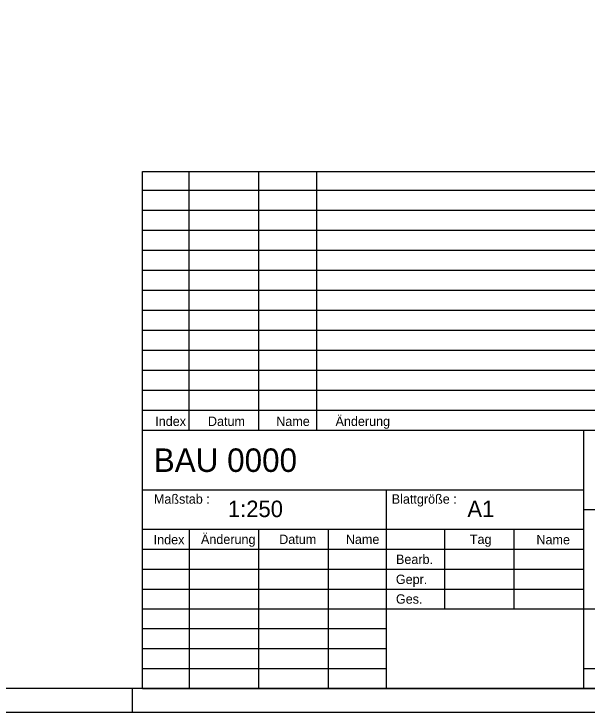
# Model space of a CAD drawing. Extents: x 0 to 210, y 0 to 148.
# Drawn here: x 157.69 to 188.16, y 0 to 37.12 of the extents above; entities that cross this region are included whole.
import ezdxf

# ---------------------------------------------------------------- set-up
doc = ezdxf.new("R2010")
doc.units = 0
doc.layers.add('90_Plankopf', color=7, linetype='Continuous')

msp = doc.modelspace()

# ---------------------------------------------------------------- linework, layer by layer
at = {"layer": '90_Plankopf'}
for p, q in [((164.53, 14.998), (164.53, 28.745)), ((164.53, 28.745), (209, 28.745)), ((167.001, 14.998), (167.001, 28.745)), ((170.707, 14.998), (170.707, 28.745)), ((173.795, 14.998), (173.795, 28.745)), ((164.53, 27.748), (209, 27.748)), ((164.53, 26.685), (209, 26.685)), ((164.53, 25.623), (209, 25.623)), ((164.53, 24.56), (209, 24.56)), ((164.53, 23.498), (209, 23.498)), ((164.53, 22.435), (209, 22.435)), ((164.53, 21.373), (209, 21.373)), ((164.53, 20.31), (209, 20.31)), ((164.53, 19.248), (209, 19.248)), ((164.53, 18.185), (209, 18.185)), ((164.53, 17.123), (209, 17.123)), ((164.53, 16.06), (209, 16.06)), ((164.53, 14.998), (209, 14.998)), ((164.53, 1.25), (164.53, 14.998)), ((164.53, 14.998), (209, 14.998)), ((188, 1.25), (188, 14.998)), ((164.53, 11.825), (188, 11.825)), ((177.501, 1.25), (177.501, 11.825)), ((188, 10.768), (209, 10.768)), ((164.53, 9.718), (188, 9.718)), ((167.001, 9.71), (167.001, 1.25)), ((170.707, 1.25), (170.707, 9.71)), ((174.412, 1.25), (174.412, 9.71)), ((180.589, 9.71), (180.589, 5.48)), ((184.294, 5.48), (184.294, 9.71)), ((164.53, 8.658), (188, 8.658)), ((164.53, 7.595), (188, 7.595)), ((164.53, 6.538), (188, 6.538)), ((164.53, 5.48), (188, 5.48)), ((164.53, 5.48), (188, 5.48)), ((177.501, 5.48), (188, 5.48)), ((188, 5.48), (209, 5.48)), ((177.501, 4.423), (164.53, 4.423)), ((177.501, 3.365), (164.53, 3.365)), ((164.53, 2.308), (177.501, 2.308)), ((188, 2.308), (209, 2.308)), ((164, 0), (164, 1.25)), ((209, 1.25), (164.53, 1.25)), ((164.53, 1.25), (177.501, 1.25)), ((167.45, 1.25), (209, 1.25)), ((167.45, 1.25), (209, 1.25))]:
    msp.add_line(p, q, dxfattribs=at)
for points in [[(0, 0), (210.25, 0), (210.25, 148.5), (0, 148.5)], [(6.25, 147.25), (209, 147.25), (209, 1.25), (6.25, 1.25)]]:
    msp.add_lwpolyline(points, close=True, dxfattribs=at)

# ---------------------------------------------------------------- texts
for s, height, p in [('Index', 0.5, (165.201, 15.214)), ('Datum', 0.5, (168.004, 15.214)), ('Name', 0.5, (171.635, 15.214)), ('Änderung', 0.5, (174.789, 15.214)), ('BAU 0000      ', 1.25, (165.123, 12.769)), ('Maßstab :', 0.5, (165.129, 11.079)), ('Blattgröße :', 0.49998, (177.779, 11.079)), ('1:250    ', 0.875, (169.065, 10.367)), ('A1       ', 0.875, (181.8, 10.367)), ('Index', 0.5, (165.117, 8.918)), ('Änderung', 0.5, (167.633, 8.937)), ('Datum', 0.5, (171.792, 8.937)), ('Name', 0.5, (175.337, 8.937)), ('Tag', 0.5, (181.931, 8.937)), ('Name', 0.5, (185.473, 8.918)), ('Bearb.', 0.5, (178.004, 7.873)), ('Gepr.', 0.5, (177.997, 6.808)), ('Ges.', 0.5, (178.001, 5.762))]:
    msp.add_text(s, height=height, dxfattribs=at).set_placement(p)

doc.saveas('drawing.dxf')
